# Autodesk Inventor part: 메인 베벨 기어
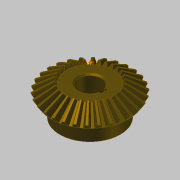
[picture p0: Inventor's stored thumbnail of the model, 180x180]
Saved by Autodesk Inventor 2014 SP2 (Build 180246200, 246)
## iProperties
Created: 2016-04
Part Number: 메인 베벨 기어
Material: 강철, 탄소
Document SubType Name: Modeling
Designer: mdu
Categories: <?xml version="1.0" encoding="UTF-16"?> <MemberInstance><Categories><FamilyTemplate><FamilyTemplateParameter ValueType="xs:double" Id="1" ObjectReferenceKey="da
Mass: 269.926 g
Surface Area: 108.837 cm^2
Volume: 34.2981 cm^3
Density: 7.87 g/cm^3
Appearance: 얼룩무늬
CustomPartVersion: 1
Author: mdu
Revision Number: 1
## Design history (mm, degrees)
node "맨 위 점"
node "메쉬 평면2"
sketch "톱니 본체 스케치"
  geometry: L1 (0, 0)-(28.669, -21.997); L2 (28.669, -21.997)-(31.109, -18.336); L3 (31.109, -18.336)-(0, 0); L4 (30, -20)-(0, 0); L5 (17.219, -13.212)-(18.685, -11.013); L6 (28.669, -21.997)-(17.219, -13.212); L7 (31.109, -18.336)-(18.685, -11.013); L8 (0, -39.387)-(0, 6.564) reference; L9 (0, -20)-(31.109, -20)
  constraints: 16 end point, 4 point on line, 3 perpendicular, 2 collinear, 1 horizontal alignment, 1 vertical alignment
  dimensions: "d0" = 60 diameter of L4.start L8 (= da_de); "d1" = 57.33744 diameter of L1.end L8 (= da_dfe); "d2" = 62.2188 diameter of L2.end L8 (= da_dae); "d3" = 14.4 distance between parallel lines of L2 L5 (= da_b); "d4" = 18.3359 vertical distance of L2.end L1.start (= da_ve)
revolve "톱니 본체" sketch "톱니 본체 스케치" stored, may be unused: angle "d5" = 90 deg
node "시작점"
node "톱니 평면"
sketch "시작 스케치"
  geometry: L1 (0, -23.505)-(0, 10.645) reference; L2 (-0.709, -2.928)-(0.709, -2.928); A1 r 19.188 centre (-19.457, -7.014) between (-0.709, -2.928) and (-3.232, 3.229); A2 r 19.188 centre (19.457, -7.014) between (3.232, 3.229) and (0.709, -2.928); A3 r 57.403 centre (0, -54.083) between (3.232, 3.229) and (-3.232, 3.229); 1 further point
  constraints: 6 point on circle, 3 centre point, 3 symmetric about line, 2 end point, 1 coincident, 1 perpendicular, 1 other
  dimensions: "d7" = 19.18795 radius of A1 (= fd_rr); "d8" = 19.45712 horizontal distance of point (0, -54.083) A1.centre (= fd_x); "d9" = 47.06905 vertical distance of point (0, -54.083) A1.centre (= fd_y); "d57" = 57.40327 radius of A3 (= 0.5 x fd_dva + 0.3 x da_he); "d58" = 51.15527 distance from line of A3.centre L2 (= 0.5 x fd_dva - 1.12 x da_he)
node "끝점"
  node "끝 평면"
sketch "3D 스케치 오른쪽"
  node "Helical Curve Right" dims "d65" = 229.90621 (computed from da_dm, da_delta, da_beta), "d66" = 31.5, "d67" = 60 (= da_de), "d68" = -9.82794 (= -da_delta), "d69" = 8.10972 (computed from fd_loft, da_delta)
node "끝 평면 오른쪽"
sketch "끝 스케치 오른쪽"
  geometry: L1 (0, -41.54)-(0, 13.178) reference; L2 (-0.422, -1.69)-(0.422, -1.69); A1 r 11.427 centre (-11.587, -4.123) between (-0.422, -1.69) and (-1.925, 1.977); A2 r 11.427 centre (11.587, -4.123) between (1.925, 1.977) and (0.422, -1.69); A3 r 34.184 centre (0, -32.153) between (1.925, 1.977) and (-1.925, 1.977); 1 further point
  constraints: 6 point on circle, 3 centre point, 3 symmetric about line, 2 end point, 1 coincident, 1 perpendicular, 1 other
  dimensions: "d70" = 11.58699 horizontal distance of A3.centre A1.centre (computed from fd_x, fd_ratio); "d71" = 28.03028 vertical distance of point (0, -32.153) A1.centre (computed from fd_y, fd_ratio); "d72" = 11.4267 radius of A1 (computed from fd_rr, fd_ratio); "d73" = 30.46369 distance from line of point (0, -32.153) L2 (computed from d58, fd_ratio); "d74" = 34.18446 radius of A3 (computed from d57, fd_ratio)
feature "로프트 오른쪽" sketch "끝 스케치 오른쪽" dims "d75" = 0, "d77" = 0, "d79" = 0, "d80" = 90 deg, "d85" = 20, "d92" = 90 deg, "d93" = 90 deg, "da_teethtype" = 0 [user parameter]
sketch "3D 스케치 왼쪽"
  node "Helical Curve Left" dims "d26" = 229.90621 (computed from da_dm, da_delta, da_beta), "d27" = 8.10972 (computed from fd_loft, da_delta), "d28" = 60 (= da_de), "d29" = -9.82794 (= -da_delta)
node "끝 평면 왼쪽"
sketch "끝 스케치 왼쪽" dims "d56" = 10.3728 (derived)
  geometry: L1 (0, -43.753)-(0, 15.405) reference; L2 (-0.422, -1.678)-(0.422, -1.678); A1 r 11.427 centre (-11.587, -4.111) between (-0.422, -1.678) and (-1.925, 1.988); A2 r 11.427 centre (11.587, -4.111) between (1.925, 1.988) and (0.422, -1.678); A3 r 34.184 centre (0, -32.142) between (1.925, 1.988) and (-1.925, 1.988); 2 further points; 1 other entity
  constraints: 6 point on circle, 3 centre point, 3 symmetric about line, 2 end point, 1 coincident, 2 other
  dimensions: "d30" = 11.4267 radius of A1 (computed from fd_rr, fd_ratio); "d31" = 11.58699 horizontal distance of point (0, -32.142) A1.centre (computed from fd_x, fd_ratio); "d32" = 28.03028 vertical distance of A1.centre point (0, -32.142) (computed from fd_y, fd_ratio); "d61" = 34.18446 radius of A3 (computed from d57, fd_ratio); "d62" = 30.46369 distance from line of point (0, -32.142) L2 (computed from d58, fd_ratio)
feature "로프트 왼쪽" sketch "끝 스케치 왼쪽" dims "d35" = 0, "d37" = 0, "d39" = 0, "d40" = 90 deg, "d84" = 10, "d90" = 90 deg, "d91" = 90 deg, "da_teethtype" = 0 [user parameter]
sketch "본체 스케치"
  geometry: L1 (0, -35.038)-(0, -19.531) reference; L2 (28.669, -21.997)-(17.219, -13.212) reference; L3 (17.219, -13.212)-(0, -13.212); L4 (28.669, -21.997)-(0, -21.997)
  constraints: 4 end point, 2 perpendicular, 2 point on line
revolve "본체 고정" sketch "본체 스케치" stored, may be unused: angle "d46" = 90 deg
feature "피치 지름" dims angle "d47" = 90 deg
sketch "스케치8"
  geometry: C1 r 22.5 at (0, 0); 1 further point
  constraints: 1 centre point, 1 coincident
  dimensions: "d94" = 45 diameter of C1
extrude "돌출1" join sketch "스케치8" distance "d95" = 13; taper "d96" = 0 deg
sketch "스케치9"
  geometry: 1 further point
hole "구멍1" sketch "스케치9" at (0, 0) diameter "d97" = 17; stored, may be unused: countersink angle "d101" = 90 deg, drill point angle "d103" = 118 deg; dims "d98" = 6, "d99" = 4, "d100" = 2, "d102" = 8
sketch "스케치10"
  geometry: L1 (8.124, 2.5)-(10.8, 2.5); L2 (10.8, 2.5)-(10.8, -2.5); L3 (10.8, -2.5)-(8.124, -2.5); A1 r 8.5 centre (0, 0) between (8.124, 2.5) and (8.124, -2.5) reference; 1 further point
  constraints: 6 end point, 2 parallel, 2 point on circle, 1 horizontal, 1 perpendicular
  dimensions: "d104" = 5 distance of L1.end L2.end; "d112" = 19.3 dimension on A1 L2
extrude "돌출2" cut sketch "스케치10" stored distance "d106" = 10; taper "d107" = 0 deg
chamfer "모따기1" distance "d108" = 1; stored, may be unused: second distance "d109" = 2, angle "d110" = 45 deg
fillet "모깎기1" dims "d111" = 2
body "Solid1"
feature "로프트" dims "d17" = 0, "d18" = 90 deg, "d19" = 0, "d20" = 90 deg, "d89" = 0, "da_teethtype" = 0 [user parameter]
pattern_circular "원형 패턴" dims angle "d22" = 360 deg, "d88" = 0, "da_teethtype" = 0 [user parameter]
pattern_circular "원형 패턴 오른쪽" dims angle "d82" = 360 deg, "da_teethtype" = 0 [user parameter]
pattern_circular "원형 패턴 왼쪽" dims angle "d42" = 360 deg, "da_teethtype" = 0 [user parameter]
sketch "끝 스케치"
  geometry: L1 (0, -15.359)-(0, 6.983) reference; L2 (-0.422, -1.69)-(0.422, -1.69); A1 r 11.427 centre (-11.587, -4.123) between (-0.422, -1.69) and (-1.925, 1.977); A2 r 11.427 centre (11.587, -4.123) between (1.925, 1.977) and (0.422, -1.69); A3 r 34.184 centre (0, -32.153) between (1.925, 1.977) and (-1.925, 1.977); 1 further point
  constraints: 6 point on circle, 3 centre point, 3 symmetric about line, 2 end point, 1 coincident, 1 other
  dimensions: "d12" = 11.4267 radius of A1 (computed from fd_rr, fd_ratio); "d15" = 11.58699 horizontal distance of A1.centre point (0, -32.153) (computed from fd_x, fd_ratio); "d16" = 28.03028 vertical distance of A1.centre point (0, -32.153) (computed from fd_y, fd_ratio); "d59" = 34.18446 radius of A3 (computed from d57, fd_ratio); "d60" = 30.46369 distance from line of A3.centre L2 (computed from d58, fd_ratio)
sketch "Sketch6"
  geometry: L1 (30, -20)-(0, 0) reference; L2 (0, -37.8)-(0, 6.3) reference
body "Srf1"
other parameters: "da_b" = 14.4 [user parameter; used in 2 equation terms], "da_de" = 60 [user parameter; used in 4 equation terms], "da_dae" = 62.2188 [user parameter; used in 2 equation terms], "da_dfe" = 57.33744 [user parameter; used in 1 equation term], "da_le" = 36.05551 [user parameter; used in 1 equation term], "da_omega" = 90 deg [user parameter; used in 1 equation term], "da_beta" = 0 [user parameter; used in 2 equation terms], "da_delta" = 9.82794 [user parameter; used in 8 equation terms], "da_alpha" = 20 deg [user parameter; used in 2 equation terms], "da_he" = 4.4 [user parameter; used in 4 equation terms], "da_ve" = 18.3359 [user parameter; used in 1 equation term], "fd_dv" = 108.16654 (computed from da_de, da_delta) [user parameter; used in 1 equation term], "fd_dva" = 112.16654 (computed from da_dae, da_delta) [user parameter; used in 3 equation terms], "fd_dvb" = 101.6433 (computed from fd_dv, da_alpha) [user parameter; used in 2 equation terms], "da_zv" = 540.83269 [user parameter; used in 1 equation term], "fd_loft" = 14.62 (= da_b + 0.05 x da_he) [user parameter; used in 4 equation terms], "fd_ratio" = 5.95514 (computed from da_le, fd_loft) [user parameter; used in 15 equation terms], "fd_rr" = 19.18795 (computed from fd_dd, fd_dvb) [user parameter; used in 6 equation terms], "fd_angle" = 0.29367 (computed from da_zv) [user parameter; used in 4 equation terms], "fd_x1" = 1.58802 (computed from da_dvw, fd_angle) [user parameter; used in 1 equation term], "fd_y1" = 54.05995 (computed from da_dvw, fd_angle) [user parameter; used in 1 equation term], "fd_x2" = 17.8691 (computed from fd_rr, fd_angle2, fd_angle) [user parameter; used in 1 equation term], "fd_y2" = 6.9909 (computed from fd_rr, fd_angle2, fd_angle) [user parameter; used in 1 equation term], "fd_x" = 19.45712 (= fd_x1 + fd_x2) [user parameter; used in 4 equation terms], "fd_y" = 47.06905 (= fd_y1 - fd_y2) [user parameter; used in 4 equation terms], "fd_angle2" = 3.43555 (computed from fd_dvb, fd_dd, da_alpha) [user parameter; used in 2 equation terms], "fd_dd" = 108.64654 (= fd_dva - 0.8 x da_he) [user parameter; used in 2 equation terms], "da_dvw" = 108.16654 [user parameter; used in 2 equation terms], "d11" = 14.62 (= fd_loft), "da_dm" = 48.01848 [user parameter; used in 2 equation terms], "da_x" = 0 [user parameter], "da_m" = 2 [user parameter], "d48" = 0, "d49" = 0, "d50" = 90 deg (= da_omega), "d51" = 6 deg (computed from da_z), "d52" = 0, "d53" = 0, "d54" = 0
